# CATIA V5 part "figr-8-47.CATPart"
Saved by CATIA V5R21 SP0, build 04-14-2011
Part number: Part1
Bounding box of the stored display mesh (mm): x -46.99 to 46.99, y -111.421 to 111.421, z 0 to 30
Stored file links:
  D:\CATIA V5R21 E-RESOURCES\CATIA-V5R21\catia-v5r21-prt\c08-catia-v5r20-prt\c08-catia-v5r21-figr-8-47.CATPart
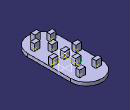
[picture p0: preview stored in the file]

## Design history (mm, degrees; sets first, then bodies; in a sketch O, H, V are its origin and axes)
Body1 (main body)
  Sketch1 on xy-plane, origin (0, 0, 0), H (1, 0, 0), V (0, 1, 0)
    construction line L1 (-46.9897, 64.4313) -> (46.9897, 64.4313)
    line L2 (46.9897, 64.4313) -> (46.9897, -64.4313)
    construction line L3 (46.9897, -64.4313) -> (-46.9897, -64.4313)
    line L4 (-46.9897, -64.4313) -> (-46.9897, 64.4313)
    axis line L5 (46.9897, -64.4313) -> (-46.9897, 64.4313)
    arc A1 centre (0, 64.4313) radius 46.9897 from (-46.9897, 64.4313) to (46.9897, 64.4313) cw
    arc A2 centre (0, -64.4313) radius 46.9897 from (-46.9897, -64.4313) to (46.9897, -64.4313) ccw
    point P7 (0, -111.4211)
    length L3 = 93.9795
    length L2 = 128.8627
    horizontal: L1 H, L3 H
    vertical: L2 V, L4 V
    midpoint: O L5
    tangency: A1 L2, A2 L4
    coincidence: A2 P7, P7 V
  Pad1: profile Sketch1, direction (0, 0, 1), length 10
  Sketch2 on face of Pad1, origin (0, 0, 10), H (1, 0, 0), V (0, 1, 0)
    line L1 (-8.4317, -82.0722) -> (8.3047, -82.0722)
    line L2 (8.3047, -82.0722) -> (8.3047, -93.8638)
    line L3 (8.3047, -93.8638) -> (-8.4317, -93.8638)
    line L4 (-8.4317, -93.8638) -> (-8.4317, -82.0722)
    horizontal: L1 H, L3 H
    vertical: L2 V, L4 V
  Pad2: profile Sketch2, direction (0, 0, 1), length 20
  Sketch3 on face of Pad1, origin (0, 0, 10), H (1, 0, 0), V (0, 1, 0)
    point P1 (-25.1683, -66.0965)
    point P2 (23.8999, -66.0965)
    point P3 (-35.058, 0)
    point P4 (35.3111, 0)
    point P5 (-25.1683, 70.4575)
    point P6 (23.8999, 70.4575)
    point P7 (0, 0)
    point P8 (0, -36.8078)
    point P9 (0, 34.322)
    coincidence: P3 H, P4 H, P7 O, P8 V, P9 V
  UserPattern1: of Pad2, copies 10, at the points of Sketch3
